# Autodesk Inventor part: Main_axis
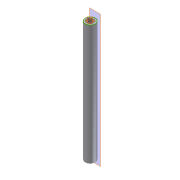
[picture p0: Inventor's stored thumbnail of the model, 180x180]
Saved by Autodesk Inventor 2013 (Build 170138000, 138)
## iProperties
Shininess: 69.0
Length Units: 11269
Angle Units: 11279
Time Units: 11290
Mass Units: 11283
Length Display Precision: 3
Angle Display Precision: 2
Created: 2001-04
Part Number: Main_axis
Material: Standard
Document SubType Name: Modellieren
Designer: dl
Density: 1 g/cm^3
Density: 0.0
Volumn: 0.0
Area: 0.0
PropertySet Name: Model Information
Control State: 0
Master: False
Checked Out: False
Author: dl
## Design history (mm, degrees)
sketch "Sketch2"
  geometry: C1 r 20 at (0, 0) reference; 1 further point
  constraints: 1 coincident
workplane "Work Plane2"
sketch "Sketch3"
  geometry: L1 (20, -480)-(-20, -480) reference; L2 (0, -480)-(0, 0); L3 (0, -250)-(0, -230); C1 r 1.562 at (0, -360); C2 r 1.562 at (0, -250); C3 r 1.562 at (0, -230); C4 r 1.562 at (0, -120); 1 further point
  constraints: 4 centre point, 4 end point, 4 vertical alignment, 3 equal radius, 3 midpoint, 1 collinear, 1 perpendicular
  dimensions: "d19" = 110 distance of L3.start C1.centre; "d20" = 20 distance of L3.end L3.start; "d21" = 110 distance of C4.centre L3.end (= d19); "d22" = 3.125 diameter of C1
extrude "Extrusion2" cut sketch "Sketch3" distance "d23" = 10; taper "d24" = 0 deg
body "Solid1"
sketch "Sketch1"
  geometry: C1 r 20 at (0, 0); C2 r 15 at (0, 0)
  constraints: 2 centre point, 1 coincident
  dimensions: "d0" = 40 diameter of C1; "d1" = 5 radial gap between concentric circles of C1 C2
extrude "Extrusion1" new body sketch "Sketch1" distance "d2" = 480; taper "d3" = 0 deg
hole "Hole1" sketch "Sketch2" diameter "d4" = 30.4; stored, may be unused: countersink angle "d8" = 60 deg, drill point angle "d10" = 0 deg; dims "d5" = 6, "d6" = 4, "d7" = 2, "d9" = 70
hole "Hole2" sketch "Sketch2" diameter "d11" = 31; stored, may be unused: countersink angle "d15" = 60 deg, drill point angle "d17" = 0 deg; dims "d12" = 6, "d13" = 4, "d14" = 2, "d16" = 10
workplane "Work Plane1"
mirror "Mirror1"
